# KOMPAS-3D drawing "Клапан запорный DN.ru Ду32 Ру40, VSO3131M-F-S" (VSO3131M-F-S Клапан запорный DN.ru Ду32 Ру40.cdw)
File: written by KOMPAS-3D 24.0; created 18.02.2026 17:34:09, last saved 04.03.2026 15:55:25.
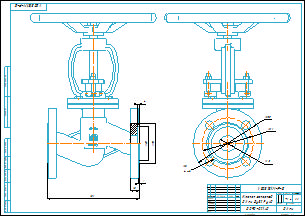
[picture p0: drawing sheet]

Document properties: Автор: R2D2; Форматы листов документа: A2; Полное имя файла: VSO3131M-F-S Клапан запорный DN.ru Ду32 Ру40.m3d; Масса: 7.04; Наименование: Клапан запорный DN.ru Ду32 Ру40; Количество листов документа: 1; Примечание: D090-02140

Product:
- Part/product: Клапан запорный DN.ru Ду32 Ру40  | designation VSO3131M-F-S
    Масса: 7.04
    Раздел спецификации: Прочие изделия
    Примечание: D090-02140

Views: Проекционный вид 2
Referenced files in E:\Работа\Зайцев\VSO3131M-F-S Клапан запорный DN.ru Ду15-100 Ру40\DN32\: VSO3131M-F-S Клапан запорный DN.ru Ду32 Ру40.m3d
Referenced files in E:\Работа\Зайцев\Для компаса\: чертеж DN.ru А3.cdt
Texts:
  VSO3131M-F-S
  чертеж DN.ru А3.cdt
  Клапан запорный
  DN.ru Ду32 Ру40
  Клапан запорный DN.ru Ду32 Ру40
  VSO3131M-F-S Клапан запорный DN.ru Ду32 Ру40
Dimensions and other numbers on the sheet: 0; 3; 5; 4; 135; 100; 32; 18; 4 отв.; 1:1; 1; 7,04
